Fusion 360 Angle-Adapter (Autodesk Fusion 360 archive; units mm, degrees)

design "Angle-Adapter" references "Base"
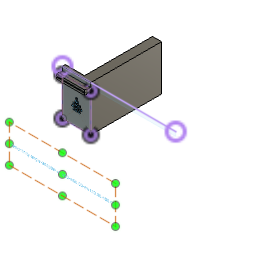
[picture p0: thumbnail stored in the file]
parameter "angle" = 90
parameter "width" = 50
parameter "extension_width" = 120
parameter "height" = 80
parameter "wall_thickness" = 5
component_insert "Component Insert"
sketch "Reference" plane through (0, 55.6118, 0) normal (0, 1, 0) x axis (-1, 0, 0)
  line L1 (0, 52.6059) -> (-200, 52.6059)
  line L2 (0, 60) -> (0, 52.6059)
  line L3 (-200, 60) -> (0, 60)
  line L4 (-200, 52.6059) -> (-200, 60)
  line L5 (-200, 60) -> (0, 60)
sketch "Base" plane through (0, 55.6118, 0) normal (0, 1, 0) x axis (-1, 0, 0)
  line L1 (-50, 60) -> (0, 60)
  line L2 (-50, -20) -> (-50, 60)
  line L3 (0, -20) -> (0, 60)
  line L4 (-50, -20) -> (0, -20)
  point P2 (0, 60)
  point P3 (-50, 60)
  point P4 (-50, -20)
  point P5 (0, -20)
  horizontal L1
  perpendicular L1 L2
  perpendicular L1 L3
  dimension "d5" distance P2 P3 = 50 (= "width")
  dimension "d7" distance P3 P4 = 80 (= "height")
  dimension "d8" distance P2 P5 = 80 (= "height")
extrude "Extrude1" new body sketch "Base" along normal blind 5 (= "wall_thickness")
extrude "Extrude2" new body of existing geometry blind 19
extrude "Extrude3" add of existing geometry to an object
extrude "Extrude4" cut of existing geometry to an object
work_plane "WorkPlane1" RotateAngle 90 (= "angle")
sketch "Sketch3" plane through (50, 0, 0) normal (1, 0, 0) x axis (0, 1, 0)
  line L1 (60.6118, -20) -> (60.6118, 60)
  line L2 (180.6118, 60) -> (60.6118, 60)
  line L3 (180.6118, -20) -> (180.6118, 60)
  line L4 (60.6118, -20) -> (180.6118, -20)
  line L5 (60.6118, 60) -> (60.6118, -20)
  point P2 (60.6118, 60)
  point P4 (60.6118, 60)
  point P3 (60.6118, -20)
  point P7 (60.6118, -20)
  point P5 (180.6118, 60)
  point P6 (180.6118, -20)
  coincident P2 P4
  perpendicular L1 L2
  perpendicular L2 L3
  coincident P3 P7
  dimension "d19" distance P4 P5 = 120 (= "extension_width")
  dimension "d20" distance P5 P6 = 80 (= "height")
extrude "Extrude5" add sketch "Sketch3" against normal blind 16 (magnitude of "( 11 mm + wall_thickness ) * -1")
extrude "Extrude6" add of existing geometry to an object
sketch "Sketch4" plane through (-0.5, 0, 0) normal (-1, 0, 0) x axis (0, -1, 0)
  line L1 (-28.6118, 45.5559) -> (-28.6118, 48.9559)
  line L2 (-33.1118, 45.5559) -> (-28.6118, 45.5559)
  line L3 (-33.1118, 47.0059) -> (-33.1118, 45.5559)
  line L4 (-39.6118, 47.0059) -> (-33.1118, 47.0059)
  line L5 (-39.6118, 39.6118) -> (-39.6118, 47.0059)
  line L6 (-22.1725, 22.1725) -> (-39.6118, 39.6118)
  line L7 (-19.6118, 60) -> (-19.6118, 23.2332)
  line L8 (-39.6118, 60) -> (-19.6118, 60)
  line L9 (-39.6118, 52.6059) -> (-39.6118, 60)
  line L10 (-33.1118, 52.6059) -> (-39.6118, 52.6059)
  line L11 (-33.1118, 54.0559) -> (-33.1118, 52.6059)
  line L12 (-28.6118, 54.0559) -> (-33.1118, 54.0559)
  line L13 (-28.6118, 50.6559) -> (-28.6118, 54.0559)
  line L14 (-33.1118, 52.6059) -> (-39.6118, 52.6059)
  line L15 (-33.1118, 52.6059) -> (-33.1118, 54.0559)
  line L16 (-33.1118, 54.0559) -> (-28.6118, 54.0559)
  line L17 (-33.1118, 45.5559) -> (-28.6118, 45.5559)
  line L18 (-33.1118, 47.0059) -> (-33.1118, 45.5559)
  line L19 (-33.1118, 47.0059) -> (-39.6118, 47.0059)
  line L20 (-28.6118, 45.5559) -> (-28.6118, 49.8059)
  line L21 (-28.6118, 54.0559) -> (-28.6118, 49.8059)
  line L22 (-39.6118, 47.0059) -> (-39.6118, 52.6059)
  arc A1 centre (-28.6118, 49.8059) radius 0.85 clockwise from (-28.6118, 50.6559) to (-28.6118, 48.9559)
  arc A2 centre (-21.1118, 23.2332) radius 1.5 clockwise from (-19.6118, 23.2332) to (-22.1725, 22.1725)
  point P15 (-39.6118, 52.6059)
  point P29 (-39.6118, 52.6059)
  point P8 (-39.6118, 47.0059)
  point P30 (-39.6118, 47.0059)
  coincident P15 P29
  coincident P8 P30
sketch "Sketch5" plane through (0, 180.6118, 0) normal (0, 1, 0) x axis (-1, 0, 0)
  line L1 (-50, -20) -> (-50, 60)
  line L2 (-34, -20) -> (-50, -20)
  line L3 (-34, 60) -> (-34, -20)
  line L4 (-50, 60) -> (-34, 60)
  line L5 (0, 52.6059) -> (-200, 52.6059)
  line L6 (-34, -20) -> (-34, 60)
  line L7 (-34, 44) -> (-34, 52.6059)
  line L8 (-40.5, 52.6059) -> (-34, 52.6059)
  line L9 (-40.5, 54.0559) -> (-40.5, 52.6059)
  line L10 (-45, 54.0559) -> (-40.5, 54.0559)
  line L11 (-45, 45.5559) -> (-45, 54.0559)
  line L12 (-40.5, 45.5559) -> (-45, 45.5559)
  line L13 (-40.5, 47.0059) -> (-40.5, 45.5559)
  line L14 (-34, 46.9975) -> (-40.5, 47.0059)
  line L15 (-34, 46.9975) -> (-34, 52.6059)
  point P10 (-34, 52.6059)
  point P11 (-34, 44)
  point P18 (-34, 46.9975)
  point P12 (-40.5, 52.6059)
  point P13 (-40.5, 54.0559)
  point P14 (-45, 54.0559)
  point P15 (-45, 45.5559)
  coincident L5 P10
  coincident L3 P10
  coincident L6 P11
  perpendicular L5 L7
  perpendicular L7 L8
  perpendicular L8 L9
  perpendicular L9 L10
  perpendicular L5 L11
  perpendicular L11 L12
  equal L10 L12
  perpendicular L12 L13
  equal L9 L13
  coincident L7 P18
  dimension "d29" distance P10 P12 = 6.5
  dimension "d30" distance P12 P13 = 1.45
  dimension "d31" distance P13 P14 = 4.5
  dimension "d32" distance P14 P15 = 8.5
extrude "Extrude9" cut sketch "Sketch5" profile of L3 L5 L6 L8 L9 L10 L11 L12 L13 L14 L15 along a picked direction to an object
sketch "Text" plane through (0, 55.6118, 0) normal (0, -1, 0) x axis (1, 0, 0)
  dimension "d35" = 3
extrude "Extrude10" cut sketch "Text" against normal blind 2
sketch "Filename" plane through (0, 0, 0) normal (0, 1, 0) x axis (1, 0, 0)
  dimension "d38" = 5

design "Base"
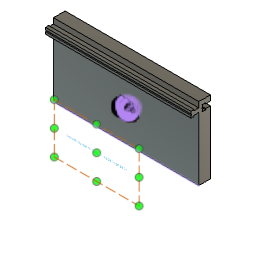
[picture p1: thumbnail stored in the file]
parameter "wall_anchor_height" = 60
parameter "wall_anchor_width" = 20
parameter "wall_anchor_angle" = 45
parameter "width_per_slot" = 40
parameter "slot_inner_width" = 8.5
parameter "slot_inner_height" = 4.5
parameter "slot_outer_width" = 5.6
parameter "slot_outer_height" = 6.5
parameter "slot_dept" = 15
parameter "print_tolerance" = 0.12
parameter "base_plate_thickness" = 16
parameter "base_plate_slot_height" = 50
parameter "wall_anchor_angle_rounded_border" = 1.5
parameter "base_plate_screw_hole_diameter" = 4
parameter "base_plate_screw_head_diameter" = 8
parameter "base_plate_screw_head_height" = 4
parameter "base_plate_screw_hole_side_distance" = 7
parameter "slot_screw_head_width" = 4.42 (= "4.3 mm + print_tolerance")
parameter "slot_screw_thread_width" = 2.12 (= "2 mm + print_tolerance")
parameter "slot_screw_head_height" = 2.12 (= "2 mm + print_tolerance")
parameter "width" = 200
parameter "filament_hole_width" = 1.7
parameter "plate_height" = 80
sketch "Side" plane through (0, 0, 0) normal (1, 0, 0) x axis (0, 1, 0)
  line L1 (39.6118, 0) -> (19.6118, 0)
  line L2 (39.6118, 60) -> (39.6118, 0)
  line L3 (19.6118, 60) -> (39.6118, 60)
  line L4 (19.6118, 0) -> (19.6118, 60)
  line L5 (39.6118, 39.6118) -> (0, 0)
  line L6 (56.0196, 0) -> (0, 0)
  point P1 (0, 0)
  point P6 (0, 0)
  point P7 (39.6118, 39.6118)
  point P2 (19.6118, 0)
  point P3 (39.6118, 0)
  point P5 (19.6118, 60)
  horizontal L1
  vertical L2
  horizontal L3
  vertical L4
  horizontal L6
  coincident P1 P6
  coincident L2 P7
  dimension "d4" distance P2 P3 = 20 (= "wall_anchor_width")
  dimension "d5" distance P2 P5 = 60 (= "wall_anchor_height")
  dimension "d6" angle L5 L6 = 45 (= "wall_anchor_angle")
extrude "Extrude1" new body sketch "Side" profile of L1 L2 L3 L4 L5 along normal blind 40 (= "width_per_slot")
sketch "Slot LeftToRight" plane through (0, 0, 0) normal (-1, 0, 0) x axis (0, -1, 0)
  line L1 (-19.6118, 60) -> (-19.6118, 19.6118)
  line L2 (-39.6118, 60) -> (-19.6118, 60)
  line L3 (-39.6118, 39.6118) -> (-39.6118, 60)
  line L4 (-19.6118, 19.6118) -> (-39.6118, 39.6118)
  line L5 (-39.6118, 52.6059) -> (-39.6118, 49.8059)
  line L6 (-39.6118, 47.0059) -> (-39.6118, 49.8059)
  line L7 (-33.1118, 52.6059) -> (-39.6118, 52.6059)
  line L8 (-28.6118, 49.8059) -> (-39.6118, 49.8059)
  line L9 (-28.6118, 54.0559) -> (-28.6118, 49.8059)
  line L10 (-33.1118, 54.0559) -> (-28.6118, 54.0559)
  line L11 (-33.1118, 52.6059) -> (-33.1118, 54.0559)
  line L12 (-28.6118, 45.5559) -> (-28.6118, 49.8059)
  line L13 (-33.1118, 45.5559) -> (-28.6118, 45.5559)
  line L14 (-33.1118, 47.0059) -> (-33.1118, 45.5559)
  line L15 (-33.1118, 47.0059) -> (-39.6118, 47.0059)
  point P6 (-39.6118, 49.8059)
  point P7 (-39.6118, 52.6059)
  point P17 (-39.6118, 47.0059)
  point P9 (-33.1118, 52.6059)
  point P16 (-33.1118, 47.0059)
  point P10 (-28.6118, 49.8059)
  point P13 (-28.6118, 49.8059)
  point P11 (-28.6118, 54.0559)
  point P14 (-28.6118, 45.5559)
  point P12 (-33.1118, 54.0559)
  point P15 (-33.1118, 45.5559)
  midpoint L3 P6
  parallel L3 L5
  parallel L3 L6
  perpendicular L3 L7
  perpendicular L6 L8
  perpendicular L8 L9
  perpendicular L9 L10
  symmetric P7 L8 P17
  symmetric P9 L8 P16
  symmetric P10 L8 P13
  symmetric L8 P11 P14
  symmetric L8 P12 P15
  dimension "d80" distance P6 P7 = 2.8 (= "slot_outer_width / 2")
  dimension "d82" distance P7 P9 = 6.5 (= "slot_outer_height")
  dimension "d84" distance P6 P10 = 11 (= "slot_outer_height + slot_inner_height")
  dimension "d85" distance P10 P11 = 4.25 (= "slot_inner_width / 2")
  dimension "d86" distance P11 P12 = 4.5 (= "slot_inner_height")
extrude "Extrude3" cut sketch "Slot LeftToRight" profile of L3 L5 L6 L7 L9 L10 L11 L12 L13 L14 L15 against normal blind 40 (magnitude of "width_per_slot * -1")
sketch "Plate" plane through (0, 39.6118, 0) normal (0, 1, 0) x axis (-1, 0, 0)
  line L1 (0, 39.6118) -> (-40, 39.6118)
  line L2 (-40, 60) -> (0, 60)
  line L3 (0, 10) -> (0, 60)
  line L4 (-40, 10) -> (-40, 60)
  line L5 (-40, 10) -> (0, 10)
  line L6 (-40, 47.0059) -> (0, 47.0059)
  line L7 (-40, 52.6059) -> (-40, 60)
  line L8 (0, 60) -> (0, 52.6059)
  line L9 (0, 52.6059) -> (-40, 52.6059)
  line L10 (-40, 60) -> (0, 60)
  line L11 (-40, 39.6118) -> (-40, 47.0059)
  line L12 (0, 47.0059) -> (0, 39.6118)
  point P2 (0, 60)
  point P3 (-40, 60)
  point P4 (0, 10)
  point P5 (-40, 10)
  perpendicular L1 L3
  perpendicular L1 L4
  dimension "d36" distance P2 P3 = 40 (= "width_per_slot")
  dimension "d37" distance P2 P4 = 50 (= "base_plate_slot_height")
  dimension "d39" distance P3 P5 = 50 (= "base_plate_slot_height")
extrude "Extrude6" new body sketch "Plate" profile of L1 L2 L3 L4 L5 L6 L7 L8 L9 L10 along normal blind 16 (= "base_plate_thickness") bodies "Base plate with slot"
sketch "Slot" plane through (0, 0, 0) normal (-1, 0, 0) x axis (0, -1, 0)
  line L1 (-19.6118, 60) -> (-19.6118, 19.6118)
  line L2 (-39.6118, 60) -> (-19.6118, 60)
  line L3 (-39.6118, 52.6059) -> (-39.6118, 60)
  line L4 (-33.1118, 52.6059) -> (-39.6118, 52.6059)
  line L5 (-33.1118, 54.0559) -> (-33.1118, 52.6059)
  line L6 (-28.6118, 54.0559) -> (-33.1118, 54.0559)
  line L7 (-28.6118, 45.5559) -> (-28.6118, 54.0559)
  line L8 (-33.1118, 45.5559) -> (-28.6118, 45.5559)
  line L9 (-33.1118, 47.0059) -> (-33.1118, 45.5559)
  line L10 (-39.6118, 47.0059) -> (-33.1118, 47.0059)
  line L11 (-39.6118, 39.6118) -> (-39.6118, 47.0059)
  line L12 (-19.6118, 19.6118) -> (-39.6118, 39.6118)
  line L13 (-33.1118, 52.6059) -> (-39.6118, 52.6059)
  line L14 (-33.1118, 54.0559) -> (-33.1118, 52.6059)
  line L15 (-28.6118, 54.0559) -> (-33.1118, 54.0559)
  line L16 (-28.6118, 45.5559) -> (-28.6118, 54.0559)
  line L17 (-33.1118, 45.5559) -> (-28.6118, 45.5559)
  line L18 (-33.1118, 47.0059) -> (-33.1118, 45.5559)
  line L19 (-39.6118, 47.0059) -> (-33.1118, 47.0059)
  line L20 (-39.6118, 10) -> (-39.6118, 60)
  line L21 (-32.9918, 52.4859) -> (-39.6118, 52.4859)
  line L22 (-32.9918, 53.9359) -> (-32.9918, 52.4859)
  line L23 (-28.7318, 53.9359) -> (-32.9918, 53.9359)
  line L24 (-28.7318, 45.6759) -> (-28.7318, 53.9359)
  line L25 (-32.9918, 45.6759) -> (-28.7318, 45.6759)
  line L26 (-32.9918, 47.1259) -> (-32.9918, 45.6759)
  line L27 (-39.6118, 47.1259) -> (-32.9918, 47.1259)
  line L28 (-33.1118, 52.6059) -> (-39.6118, 52.6059)
  line L29 (-33.1118, 52.6059) -> (-33.1118, 54.0559)
  line L30 (-28.6118, 54.0559) -> (-33.1118, 54.0559)
  line L31 (-28.6118, 45.5559) -> (-28.6118, 54.0559)
  line L32 (-33.1118, 45.5559) -> (-28.6118, 45.5559)
  line L33 (-33.1118, 47.0059) -> (-33.1118, 45.5559)
  line L34 (-39.6118, 47.0059) -> (-33.1118, 47.0059)
  line L35 (-39.6118, 47.0059) -> (-39.6118, 52.6059)
  line L36 (-49.1118, 52.6059) -> (-55.6118, 52.6059)
  line L37 (-49.1118, 52.6059) -> (-49.1118, 54.0559)
  line L38 (-44.6118, 54.0559) -> (-49.1118, 54.0559)
  line L39 (-44.6118, 45.5559) -> (-44.6118, 54.0559)
  line L40 (-49.1118, 45.5559) -> (-44.6118, 45.5559)
  line L41 (-49.1118, 47.0059) -> (-49.1118, 45.5559)
  line L42 (-55.6118, 47.0059) -> (-49.1118, 47.0059)
  line L43 (-55.6118, 47.0059) -> (-55.6118, 52.6059)
  point P15 (-39.6118, 52.6059)
  point P33 (-39.6118, 52.6059)
  point P16 (-33.1118, 52.6059)
  point P34 (-33.1118, 52.6059)
  point P17 (-33.1118, 54.0559)
  point P35 (-33.1118, 54.0559)
  point P36 (-33.1118, 52.6059)
  point P18 (-28.6118, 54.0559)
  point P37 (-28.6118, 54.0559)
  point P19 (-28.6118, 45.5559)
  point P38 (-28.6118, 45.5559)
  point P10 (-28.6118, 45.5559)
  point P39 (-28.6118, 45.5559)
  point P11 (-33.1118, 45.5559)
  point P40 (-33.1118, 45.5559)
  point P41 (-33.1118, 45.5559)
  point P12 (-33.1118, 47.0059)
  point P42 (-33.1118, 47.0059)
  point P21 (-33.1118, 47.0059)
  point P43 (-33.1118, 47.0059)
  point P22 (-39.6118, 47.0059)
  point P44 (-39.6118, 47.0059)
  point P45 (-39.6118, 52.6059)
  point P46 (-39.6118, 47.0059)
  coincident P15 P33
  coincident P16 P34
  coincident P17 P35
  coincident P16 P36
  coincident P18 P37
  coincident P19 P38
  coincident P10 P39
  coincident P11 P40
  coincident P11 P41
  coincident P12 P42
  coincident P21 P43
  coincident P22 P44
  coincident P15 P45
  coincident P22 P46
  dimension "d91" = 0.12 (= "print_tolerance")
  dimension "d96" R-Pattern1-uDistance = -16 (= "base_plate_thickness * -1")
  dimension "d97" R-Pattern1-vDistance = 0
extrude "Extrude7" add sketch "Slot" profile of L20 L24 L23 L27 L22 L25 L26 L21 against normal blind 40 (magnitude of "width_per_slot * -1")
extrude "Extrude8" cut sketch "Slot" profile of L36 L37 L38 L39 L40 L41 L42 L43 no distance stored
sketch "Sketch3" plane through (0, 0, 0) normal (-1, 0, 0) x axis (0, -1, 0)
  line L1 (-32.9918, 47.1259) -> (-39.6118, 47.1259)
  line L2 (-32.9918, 45.6759) -> (-32.9918, 47.1259)
  line L3 (-28.7318, 45.6759) -> (-32.9918, 45.6759)
  line L4 (-28.7318, 53.9359) -> (-28.7318, 45.6759)
  line L5 (-32.9918, 53.9359) -> (-28.7318, 53.9359)
  line L6 (-32.9918, 52.4859) -> (-32.9918, 53.9359)
  line L7 (-39.6118, 52.4859) -> (-32.9918, 52.4859)
  line L8 (-44.6118, 45.5559) -> (-44.6118, 54.0559)
  line L9 (-32.9918, 52.4859) -> (-39.6118, 52.4859)
  line L10 (-32.9918, 53.9359) -> (-32.9918, 52.4859)
  line L11 (-28.7318, 53.9359) -> (-32.9918, 53.9359)
  line L12 (-28.7318, 45.6759) -> (-28.7318, 53.9359)
  line L13 (-32.9918, 45.6759) -> (-28.7318, 45.6759)
  line L14 (-32.9918, 47.1259) -> (-32.9918, 45.6759)
  line L15 (-39.6118, 47.1259) -> (-32.9918, 47.1259)
  line L16 (-39.6118, 47.1259) -> (-39.6118, 52.4859)
  line L17 (-55.6118, 52.4859) -> (-48.9918, 52.4859)
  line L18 (-48.9918, 52.4859) -> (-48.9918, 53.9359)
  line L19 (-48.9918, 53.9359) -> (-44.7318, 53.9359)
  line L20 (-44.7318, 45.6759) -> (-44.7318, 53.9359)
  line L21 (-48.9918, 45.6759) -> (-44.7318, 45.6759)
  line L22 (-48.9918, 47.1259) -> (-48.9918, 45.6759)
  line L23 (-55.6118, 47.1259) -> (-48.9918, 47.1259)
  line L24 (-55.6118, 47.1259) -> (-55.6118, 52.4859)
  line L25 (-55.6118, 47.0059) -> (-49.1118, 47.0059)
  line L26 (-55.6118, 10) -> (-55.6118, 47.0059)
  line L27 (-39.6118, 10) -> (-55.6118, 10)
  line L28 (-39.6118, 47.1259) -> (-39.6118, 10)
  line L29 (-39.6118, 60) -> (-39.6118, 52.4859)
  line L30 (-55.6118, 60) -> (-39.6118, 60)
  line L31 (-55.6118, 52.6059) -> (-55.6118, 60)
  line L32 (-49.1118, 52.6059) -> (-55.6118, 52.6059)
  line L33 (-49.1118, 54.0559) -> (-49.1118, 52.6059)
  line L34 (-44.6118, 54.0559) -> (-49.1118, 54.0559)
  line L35 (-49.1118, 45.5559) -> (-44.6118, 45.5559)
  line L36 (-49.1118, 47.0059) -> (-49.1118, 45.5559)
  point P9 (-39.6118, 52.4859)
  point P20 (-39.6118, 52.4859)
  point P19 (-39.6118, 47.1259)
  point P21 (-39.6118, 47.1259)
  coincident P9 P20
  coincident P19 P21
  dimension "d105" R-Pattern1-vDistance = 0
extrude "Extrude3" new body sketch "Sketch3" profile of L17 L18 L19 L20 L21 L22 L23 L24 against normal blind 40 (magnitude of "width_per_slot * -1")
sketch "Screw hole" plane through (0, 28.6118, 0) normal (0, 1, 0) x axis (-1, 0, 0)
  line L1 (0, 54.0559) -> (0, 45.5559)
  line L2 (-40, 54.0559) -> (0, 54.0559)
  line L3 (-40, 45.5559) -> (-40, 54.0559)
  line L4 (0, 45.5559) -> (-40, 45.5559)
  line L5 (0, 45.5559) -> (-40, 54.0559)
  line L6 (-40, 45.5559) -> (0, 54.0559)
  circle C1 centre (-20, 49.8059) radius 2.21
  circle C2 centre (-20, 49.8059) radius 1.06
  point P4 (-40, 54.0559)
  point P6 (-40, 54.0559)
  point P2 (0, 45.5559)
  point P7 (0, 45.5559)
  point P3 (0, 54.0559)
  point P8 (0, 54.0559)
  point P5 (-40, 45.5559)
  point P9 (-40, 45.5559)
  point P10 (-20, 49.8059)
  coincident P4 P6
  coincident P2 P7
  coincident P3 P8
  coincident P5 P9
  midpoint L5 P10
  concentric C1 C2
  dimension "d119" diameter C1 = 4.42 (= "slot_screw_head_width")
  dimension "d120" diameter C2 = 2.12 (= "slot_screw_thread_width")
extrude "Extrude4" cut sketch "Screw hole" profile of C2 against normal blind 2000
extrude "Extrude5" cut sketch "Screw hole" profile of C1 C2 no distance stored
fillet "Fillet1" radius 1.5 (= "wall_anchor_angle_rounded_border")
work_plane "WorkPlane1" sketch "Slot LeftToRight" AlongDistance -20 (= "-width_per_slot / 2")
sketch "Screw head" plane through (20, 0, 0) normal (-1, 0, 0) x axis (0, -1, 0)
  line L1 (-28.6118, 52.0159) -> (-28.6118, 47.5959)
  line L2 (-26.4918, 52.0159) -> (-26.4918, 47.5959)
  line L3 (-26.4918, 48.7459) -> (-26.4918, 50.8659)
  line L4 (-26.4918, 50.8659) -> (-28.6118, 52.0159)
  line L5 (-26.4918, 52.0159) -> (-28.6118, 52.0159)
  point P3 (-28.6118, 52.0159)
  point P8 (-28.6118, 52.0159)
  point P6 (-26.4918, 50.8659)
  point P9 (-26.4918, 50.8659)
  point P10 (-28.6118, 52.0159)
  point P5 (-26.4918, 52.0159)
  point P11 (-26.4918, 52.0159)
  coincident P3 P8
  coincident P6 P9
  coincident P3 P10
  coincident P5 P11
revolve "Revolve1" sketch "Screw head" AlongAngle 360
sketch "Plate" plane through (0, 39.6118, 0) normal (0, 1, 0) x axis (-1, 0, 0)
  line L1 (0, 39.6118) -> (-40, 39.6118)
  line L2 (-40, 60) -> (0, 60)
  line L3 (0, 10) -> (0, 60)
  line L4 (-40, 10) -> (-40, 60)
  line L5 (-40, 10) -> (0, 10)
  line L6 (-40, 47.0059) -> (0, 47.0059)
  line L7 (-40, 39.6118) -> (-40, 47.0059)
  line L8 (0, 47.0059) -> (0, 39.6118)
  line L9 (0, 52.6059) -> (-40, 52.6059)
  line L10 (-40, 60) -> (0, 60)
  line L11 (0, 60) -> (0, 52.6059)
  line L12 (-40, 52.6059) -> (-40, 60)
  point P2 (0, 60)
  point P3 (-40, 60)
  point P4 (0, 10)
  point P5 (-40, 10)
  perpendicular L1 L3
  perpendicular L1 L4
  dimension "d36_1" distance P2 P3 = 40 (= "width_per_slot")
  dimension "d37_1" distance P2 P4 = 50 (= "base_plate_slot_height")
  dimension "d39_1" distance P3 P5 = 50 (= "base_plate_slot_height")
extrude "Extrude6" new body sketch "Plate" profile of L1 L2 L3 L4 L5 L6 L7 L8 L9 L10 along normal blind 16 (= "base_plate_thickness") named "d89_1" bodies "Base plate with slot"
sketch "Slot" plane through (0, 0, 0) normal (-1, 0, 0) x axis (0, -1, 0)
  line L1 (-19.6118, 60) -> (-19.6118, 23.2332)
  line L2 (-39.6118, 60) -> (-19.6118, 60)
  line L3 (-39.6118, 52.6059) -> (-39.6118, 60)
  line L4 (-33.1118, 52.6059) -> (-39.6118, 52.6059)
  line L5 (-33.1118, 54.0559) -> (-33.1118, 52.6059)
  line L6 (-28.6118, 54.0559) -> (-33.1118, 54.0559)
  line L7 (-28.6118, 45.5559) -> (-28.6118, 54.0559)
  line L8 (-33.1118, 45.5559) -> (-28.6118, 45.5559)
  line L9 (-33.1118, 47.0059) -> (-33.1118, 45.5559)
  line L10 (-39.6118, 47.0059) -> (-33.1118, 47.0059)
  line L11 (-39.6118, 39.6118) -> (-39.6118, 47.0059)
  line L12 (-22.1725, 22.1725) -> (-39.6118, 39.6118)
  line L13 (-33.1118, 52.6059) -> (-39.6118, 52.6059)
  line L14 (-33.1118, 54.0559) -> (-33.1118, 52.6059)
  line L15 (-28.6118, 54.0559) -> (-33.1118, 54.0559)
  line L16 (-28.6118, 45.5559) -> (-28.6118, 54.0559)
  line L17 (-33.1118, 45.5559) -> (-28.6118, 45.5559)
  line L18 (-33.1118, 47.0059) -> (-33.1118, 45.5559)
  line L19 (-39.6118, 47.0059) -> (-33.1118, 47.0059)
  line L20 (-39.6118, 10) -> (-39.6118, 60)
  line L21 (-32.9918, 52.4859) -> (-39.6118, 52.4859)
  line L22 (-32.9918, 53.9359) -> (-32.9918, 52.4859)
  line L23 (-28.7318, 53.9359) -> (-32.9918, 53.9359)
  line L24 (-28.7318, 45.6759) -> (-28.7318, 53.9359)
  line L25 (-32.9918, 45.6759) -> (-28.7318, 45.6759)
  line L26 (-32.9918, 47.1259) -> (-32.9918, 45.6759)
  line L27 (-39.6118, 47.1259) -> (-32.9918, 47.1259)
  line L28 (-33.1118, 52.6059) -> (-39.6118, 52.6059)
  line L29 (-33.1118, 52.6059) -> (-33.1118, 54.0559)
  line L30 (-28.6118, 54.0559) -> (-33.1118, 54.0559)
  line L31 (-28.6118, 45.5559) -> (-28.6118, 54.0559)
  line L32 (-33.1118, 45.5559) -> (-28.6118, 45.5559)
  line L33 (-33.1118, 47.0059) -> (-33.1118, 45.5559)
  line L34 (-39.6118, 47.0059) -> (-33.1118, 47.0059)
  line L35 (-39.6118, 47.0059) -> (-39.6118, 52.6059)
  line L36 (-49.1118, 52.6059) -> (-55.6118, 52.6059)
  line L37 (-49.1118, 52.6059) -> (-49.1118, 54.0559)
  line L38 (-44.6118, 54.0559) -> (-49.1118, 54.0559)
  line L39 (-44.6118, 45.5559) -> (-44.6118, 54.0559)
  line L40 (-49.1118, 45.5559) -> (-44.6118, 45.5559)
  line L41 (-49.1118, 47.0059) -> (-49.1118, 45.5559)
  line L42 (-55.6118, 47.0059) -> (-49.1118, 47.0059)
  line L43 (-55.6118, 47.0059) -> (-55.6118, 52.6059)
  arc A1 centre (-21.1118, 23.2332) radius 1.5 clockwise from (-19.6118, 23.2332) to (-22.1725, 22.1725)
  point P15 (-39.6118, 52.6059)
  point P33 (-39.6118, 52.6059)
  point P16 (-33.1118, 52.6059)
  point P34 (-33.1118, 52.6059)
  point P17 (-33.1118, 54.0559)
  point P35 (-33.1118, 54.0559)
  point P36 (-33.1118, 52.6059)
  point P18 (-28.6118, 54.0559)
  point P37 (-28.6118, 54.0559)
  point P19 (-28.6118, 45.5559)
  point P38 (-28.6118, 45.5559)
  point P10 (-28.6118, 45.5559)
  point P39 (-28.6118, 45.5559)
  point P11 (-33.1118, 45.5559)
  point P40 (-33.1118, 45.5559)
  point P41 (-33.1118, 45.5559)
  point P12 (-33.1118, 47.0059)
  point P42 (-33.1118, 47.0059)
  point P21 (-33.1118, 47.0059)
  point P43 (-33.1118, 47.0059)
  point P22 (-39.6118, 47.0059)
  point P44 (-39.6118, 47.0059)
  point P45 (-39.6118, 52.6059)
  point P46 (-39.6118, 47.0059)
  coincident P15 P33
  coincident P16 P34
  coincident P17 P35
  coincident P16 P36
  coincident P18 P37
  coincident P19 P38
  coincident P10 P39
  coincident P11 P40
  coincident P11 P41
  coincident P12 P42
  coincident P21 P43
  coincident P22 P44
  coincident P15 P45
  coincident P22 P46
  dimension "d91_1" = 0.12 (= "print_tolerance")
  dimension "d96_1" R-Pattern1-uDistance = -16 (= "base_plate_thickness * -1")
  dimension "d97_1" R-Pattern1-vDistance = 0
extrude "Extrude8" cut sketch "Slot" profile of L36 L37 L38 L39 L40 L41 L42 L43 no distance stored
sketch "Screw" plane through (0, 55.6118, 0) normal (0, 1, 0) x axis (-1, 0, 0)
  line L1 (-40, 47.0059) -> (0, 47.0059)
  line L2 (-40, 10) -> (-40, 47.0059)
  line L3 (0, 10) -> (-40, 10)
  line L4 (0, 47.0059) -> (0, 10)
  line L5 (-33, 17) -> (-33, 40.0059)
  line L6 (-7, 17) -> (-33, 17)
  line L7 (-7, 40.0059) -> (-7, 17)
  line L8 (-33, 40.0059) -> (-7, 40.0059)
  circle C1 centre (-33, 17) radius 4
  circle C2 centre (-33, 17) radius 2
  point P7 (-33, 17)
  point P10 (-33, 17)
  coincident P7 P10
  concentric C1 C2
  dimension "d127" = -7 (= "base_plate_screw_hole_side_distance * -1")
  dimension "d128" diameter C1 = 8
  dimension "d129" diameter C2 = 4
rectangular_pattern "R-Pattern2" countU 5 (= "floor(( width / mm ) / ( width_per_slot / cm * 10 ))") uSpaceDistance 40 (= "width_per_slot") vSpaceDistance 0 bodies "Wall anchor part (1)", "Wall anchor part (2)", "Wall anchor part (3)", "Wall anchor part (4)"
work_plane "WorkPlane2"
extrude "Extrude12" new body of existing geometry no distance stored
mirror "Mirror3" mirrorStitchTolerance 0.1
sketch "filename" plane through (0, 19.6118, 0) normal (0, -1, 0) x axis (1, 0, 0)
  dimension "d216" = 3
sketch "Text" plane through (0, 19.6118, 0) normal (0, -1, 0) x axis (1, 0, 0)
  line L1 (200.5, 60) -> (200.5, 23.2332)
  line L2 (200, 23.2332) -> (200, 60)
  line L3 (200.5, 23.2332) -> (200, 23.2332)
  line L4 (200.5, 60) -> (200.5, 23.2332)
  line L5 (200, 60) -> (200.5, 60)
  line L6 (0, 60) -> (0, 23.2332)
  line L7 (-0.5, 60) -> (0, 60)
  line L8 (-0.5, 23.2332) -> (-0.5, 60)
  line L9 (0, 23.2332) -> (-0.5, 23.2332)
  curve K1
  curve K2
  curve K3
  curve K4
  line L10 (80, 60) -> (40, 60)
  point P4 (200.5, 23.2332)
  point P2 (-0.5, 60)
  coincident P4
  coincident P2
  parallel K3 L10
  dimension "d229" Text1-Height = 3
extrude "Extrude19" cut sketch "Text" against normal blind 2
extrude "Extrude14" cut of existing geometry blind 80 (= "( width_per_slot - width ) / -2")
extrude "Extrude15" cut of existing geometry blind 80 (= "( width_per_slot - width ) / -2")
extrude "Extrude9" cut of existing geometry blind -39 (= "-width_per_slot + 1 mm")
extrude "Extrude10" add of existing geometry blind 199 (= "width - 1 mm")
extrude "Extrude13" cut of existing geometry blind -30
extrude "Extrude14" add of existing geometry blind 80 (= "plate_height")
sketch "Sketch7" plane through (0, 39.6118, 0) normal (0, -1, 0) x axis (1, 0, 0)
  dimension "d236" = 3
extrude "Extrude11" cut sketch "Sketch7" against normal blind 2
sketch "File name" plane through (0, 39.6118, 0) normal (0, -1, 0) x axis (1, 0, 0)
  line L1 (92.897, 7.4163) -> (92.6596, 7.4163)
  line L2 (92.897, 4.404) -> (92.897, 7.4163)
  line L3 (92.5286, 4.404) -> (92.897, 4.404)
  line L4 (92.5286, 6.7512) -> (92.5286, 4.404)
  curve K1 (92.1787, 6.4975) -> (92.5286, 6.7512)
  curve K2 (91.792, 6.3072) -> (92.1787, 6.4975)
  line L5 (91.792, 6.6632) -> (91.792, 6.3072)
  curve K3 (92.3322, 7.0152) -> (91.792, 6.6632)
  curve K4 (92.6596, 7.4163) -> (92.3322, 7.0152)
  line L6 (96.1242, 4.404) -> (96.5641, 6.0759)
  line L7 (95.7394, 4.404) -> (96.1242, 4.404)
  line L8 (95.0744, 6.5773) -> (95.7394, 4.404)
  line L9 (95.455, 6.5773) -> (95.0744, 6.5773)
  line L10 (95.8008, 5.3229) -> (95.455, 6.5773)
  line L11 (95.9297, 4.8563) -> (95.8008, 5.3229)
  curve K5 (96.0423, 5.3044) -> (95.9297, 4.8563)
  line L12 (96.3881, 6.5773) -> (96.0423, 5.3044)
  line L13 (96.7667, 6.5773) -> (96.3881, 6.5773)
  line L14 (97.0921, 5.3167) -> (96.7667, 6.5773)
  line L15 (97.2005, 4.9013) -> (97.0921, 5.3167)
  line L16 (97.3254, 5.3208) -> (97.2005, 4.9013)
  line L17 (97.6978, 6.5773) -> (97.3254, 5.3208)
  line L18 (98.0559, 6.5773) -> (97.6978, 6.5773)
  line L19 (97.3765, 4.404) -> (98.0559, 6.5773)
  line L20 (96.9939, 4.404) -> (97.3765, 4.404)
  line L21 (96.648, 5.7055) -> (96.9939, 4.404)
  line L22 (96.5641, 6.0759) -> (96.648, 5.7055)
  line L23 (94.9311, 5.3044) -> (94.9311, 5.6748)
  line L24 (93.7995, 5.3044) -> (94.9311, 5.3044)
  line L25 (93.7995, 5.6748) -> (93.7995, 5.3044)
  line L26 (94.9311, 5.6748) -> (93.7995, 5.6748)
  line L27 (90.4638, 4.404) -> (91.2865, 6.5773)
  line L28 (90.1201, 4.404) -> (90.4638, 4.404)
  line L29 (89.2933, 6.5773) -> (90.1201, 4.404)
  line L30 (89.6821, 6.5773) -> (89.2933, 6.5773)
  line L31 (90.1487, 5.2758) -> (89.6821, 6.5773)
  curve K6 (90.2879, 4.8379) -> (90.1487, 5.2758)
  curve K7 (90.425, 5.2512) -> (90.2879, 4.8379)
  line L32 (90.9079, 6.5773) -> (90.425, 5.2512)
  line L33 (91.2865, 6.5773) -> (90.9079, 6.5773)
  line L34 (0, 47.1259) -> (200, 47.1259)
  line L35 (0, -40) -> (0, 47.1259)
  line L36 (200, 47.1259) -> (200, -40)
  curve K8
  curve K9
  curve K10
  curve K11
  curve K12 (100.1944, 6.5834) -> (99.9427, 7.1769)
  line L37 (200, -40) -> (0, -40)
  line L38 (100.1985, 4.404) -> (100.1985, 4.758)
  curve K13 (99.9427, 7.1769) -> (99.2592, 7.4163)
  curve K14 (101.5716, 7.4163) -> (101.0273, 7.2403)
  line L39 (98.2156, 4.404) -> (100.1985, 4.404)
  curve K15 (96.1252, 1.9443) -> (95.4744, 1.6455)
  curve K16 (99.074, 1.5862) -> (99.1845, 1.9504)
  curve K17 (98.7425, 1.3488) -> (99.074, 1.5862)
  curve K18 (99.162, 1.0582) -> (98.7425, 1.3488)
  curve K19 (100.1207, 6.2294) -> (100.1944, 6.5834)
  curve K20 (102.296, 7.0377) -> (101.9952, 7.3181)
  curve K21 (102.4823, 6.5916) -> (102.296, 7.0377)
  curve K22 (102.5498, 5.8836) -> (102.4823, 6.5916)
  curve K23 (102.4413, 5.0302) -> (102.5498, 5.8836)
  curve K24 (103.2691, 2.0568) -> (103.1606, 1.2014)
  curve K25 (97.9014, 1.3488) -> (97.4778, 1.0786)
  curve K26 (106.4195, 5.8836) -> (106.7162, 4.6639)
  curve K27 (96.3871, 1.5002) -> (96.5078, 1.0991)
  curve K28 (99.3083, 5.3351) -> (99.8752, 5.8631)
  curve K29 (98.8827, 4.9566) -> (99.3083, 5.3351)
  curve K30 (98.7271, 4.758) -> (98.8827, 4.9566)
  curve K31 (100.7019, 6.7389) -> (100.5935, 5.8836)
  curve K32 (101.0273, 7.2403) -> (100.7019, 6.7389)
  curve K33 (98.2585, 4.6598) -> (98.2156, 4.404)
  curve K34 (98.5, 5.0589) -> (98.2585, 4.6598)
  curve K35 (99.6439, 6.1475) -> (98.983, 5.5132)
  curve K36 (99.8158, 6.5916) -> (99.6439, 6.1475)
  curve K37 (104.1388, -0.3293) -> (104.6832, -0.1533)
  curve K38 (108.8588, 6.7389) -> (108.7503, 5.8836)
  line L40 (92.7752, -1.111) -> (93.1436, -1.111)
  curve K39 (96.0495, 1.6271) -> (96.3871, 1.5002)
  curve K40 (95.7405, 1.5411) -> (96.0495, 1.6271)
  curve K41 (95.5358, 1.3119) -> (95.7405, 1.5411)
  curve K42 (95.4744, 0.9108) -> (95.5358, 1.3119)
  curve K43 (106.528, 6.7389) -> (106.4195, 5.8836)
  curve K44 (98.6637, 6.5098) -> (98.8254, 6.9518)
  curve K45 (98.5778, 7.1932) -> (98.2851, 6.5486)
  curve K46 (99.2592, 7.4163) -> (98.5778, 7.1932)
  curve K47 (102.116, 4.5289) -> (102.4413, 5.0302)
  curve K48 (101.5716, 4.3529) -> (102.116, 4.5289)
  curve K49 (100.8902, 4.6639) -> (101.5716, 4.3529)
  curve K50 (100.5935, 5.8836) -> (100.8902, 4.6639)
  line L41 (100.1985, 4.758) -> (98.7271, 4.758)
  curve K51 (98.983, 5.5132) -> (98.5, 5.0589)
  curve K52 (99.6583, 6.96) -> (99.8158, 6.5916)
  curve K53 (99.251, 7.1114) -> (99.6583, 6.96)
  curve K54 (98.8254, 6.9518) -> (99.251, 7.1114)
  line L42 (98.2851, 6.5486) -> (98.6637, 6.5098)
  curve K55 (99.8752, 5.8631) -> (100.1207, 6.2294)
  curve K56 (103.9025, 7.4163) -> (103.3581, 7.2403)
  curve K57 (104.3261, 7.3181) -> (103.9025, 7.4163)
  curve K58 (104.8131, 6.5916) -> (104.6269, 7.0377)
  curve K59 (104.8806, 5.8836) -> (104.8131, 6.5916)
  curve K60 (107.3977, 4.3529) -> (107.942, 4.5289)
  curve K61 (106.7162, 4.6639) -> (107.3977, 4.3529)
  line L43 (93.1436, -1.111) -> (93.1436, -0.053)
  line L44 (95.4744, -0.2781) -> (95.4744, 0.9108)
  line L45 (95.1061, -0.2781) -> (95.4744, -0.2781)
  curve K62 (98.9451, 2.505) -> (98.3128, 2.7342)
  curve K63 (99.1845, 1.9504) -> (98.9451, 2.505)
  line L46 (93.1108, 1.6128) -> (93.1108, 1.8952)
  curve K64 (101.9952, 7.3181) -> (101.5716, 7.4163)
  line L47 (105.8813, 4.404) -> (105.8813, 4.8235)
  line L48 (105.4618, 4.404) -> (105.8813, 4.404)
  line L49 (105.4618, 4.8235) -> (105.4618, 4.404)
  line L50 (105.8813, 4.8235) -> (105.4618, 4.8235)
  curve K65 (106.8533, 7.2403) -> (106.528, 6.7389)
  curve K66 (107.3977, 7.4163) -> (106.8533, 7.2403)
  curve K67 (107.8213, 7.3181) -> (107.3977, 7.4163)
  curve K68 (108.1221, 7.0377) -> (107.8213, 7.3181)
  curve K69 (108.3083, 6.5916) -> (108.1221, 7.0377)
  curve K70 (108.3759, 5.8836) -> (108.3083, 6.5916)
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  dimension "d239" Text1-Height = 3
sketch "Sketch4" plane through (40, 0, 0) normal (1, 0, 0) x axis (0, 1, 0)
  line L1 (44.7318, 53.9359) -> (48.9918, 53.9359)
  line L2 (44.7318, 45.6759) -> (44.7318, 53.9359)
  line L3 (48.9918, 45.6759) -> (44.7318, 45.6759)
  line L4 (48.9918, 47.1259) -> (48.9918, 45.6759)
  line L5 (55.6118, 47.1259) -> (48.9918, 47.1259)
  line L6 (55.6118, 52.4859) -> (55.6118, 47.1259)
  line L7 (48.9918, 52.4859) -> (55.6118, 52.4859)
  line L8 (48.9918, 53.9359) -> (48.9918, 52.4859)
  circle C1 centre (44.7318, 49.8059) radius 0.85
  point P10 (44.7318, 49.8059)
  midpoint L2 P10
  dimension "d241" diameter C1 = 1.7 (= "filament_hole_width")
extrude "Extrude4" cut sketch "Sketch4" profile of L2 C1 no distance stored
sketch "Sketch15" plane through (-0.5, 0, 0) normal (-1, 0, 0) x axis (0, -1, 0)
  line L1 (-19.6118, 60) -> (-19.6118, 23.2332)
  line L2 (-39.6118, 60) -> (-19.6118, 60)
  line L3 (-39.6118, 52.6059) -> (-39.6118, 60)
  line L4 (-33.1118, 52.6059) -> (-39.6118, 52.6059)
  line L5 (-33.1118, 54.0559) -> (-33.1118, 52.6059)
  line L6 (-28.6118, 54.0559) -> (-33.1118, 54.0559)
  line L7 (-28.6118, 45.5559) -> (-28.6118, 54.0559)
  line L8 (-33.1118, 45.5559) -> (-28.6118, 45.5559)
  line L9 (-33.1118, 47.0059) -> (-33.1118, 45.5559)
  line L10 (-39.6118, 47.0059) -> (-33.1118, 47.0059)
  line L11 (-39.6118, 39.6118) -> (-39.6118, 47.0059)
  line L12 (-22.1725, 22.1725) -> (-39.6118, 39.6118)
  arc A1 centre (-21.1118, 23.2332) radius 1.5 clockwise from (-19.6118, 23.2332) to (-22.1725, 22.1725)
  circle C1 centre (-28.6118, 49.8059) radius 0.85
  point P16 (-28.6118, 49.8059)
  midpoint L7 P16
  dimension "d244" diameter C1 = 1.7 (= "filament_hole_width")
sketch "Sketch9" plane through (200, 0, 0) normal (1, 0, 0) x axis (0, 1, 0)
  line L1 (49.1118, 47.0059) -> (55.6118, 47.0059)
  line L2 (49.1118, 45.5559) -> (49.1118, 47.0059)
  line L3 (44.6118, 45.5559) -> (49.1118, 45.5559)
  line L4 (44.6118, 54.0559) -> (44.6118, 45.5559)
  line L5 (49.1118, 54.0559) -> (44.6118, 54.0559)
  line L6 (49.1118, 52.6059) -> (49.1118, 54.0559)
  line L7 (55.6118, 52.6059) -> (49.1118, 52.6059)
  line L8 (55.6118, 47.0059) -> (55.6118, -40)
  line L9 (39.6118, 60) -> (55.6118, 60)
  line L10 (39.6118, 52.4859) -> (39.6118, 60)
  line L11 (32.9918, 52.4859) -> (39.6118, 52.4859)
  line L12 (32.9918, 53.9359) -> (32.9918, 52.4859)
  line L13 (28.7318, 53.9359) -> (32.9918, 53.9359)
  line L14 (28.7318, 45.6759) -> (28.7318, 53.9359)
  line L15 (32.9918, 45.6759) -> (28.7318, 45.6759)
  line L16 (32.9918, 47.1259) -> (32.9918, 45.6759)
  line L17 (39.6118, 47.1259) -> (32.9918, 47.1259)
  line L18 (55.6118, 60) -> (55.6118, 52.6059)
  line L19 (39.6118, -40) -> (39.6118, 47.1259)
  line L20 (55.6118, -40) -> (39.6118, -40)
  circle C1 centre (28.7318, 49.8059) radius 0.85
  circle C2 centre (44.6118, 49.8059) radius 0.85
  point P20 (28.7318, 49.8059)
  point P21 (44.6118, 49.8059)
  midpoint L14 P20
  midpoint L4 P21
  dimension "d247" diameter C1 = 1.7 (= "filament_hole_width")
  dimension "d250" diameter C2 = 1.7 (= "filament_hole_width")
extrude "Extrude12" cut sketch "Sketch9" profile of L4 L14 C1 C2 no distance stored
sketch "Sketch16" plane through (0, 19.6118, 0) normal (0, -1, 0) x axis (1, 0, 0)
  dimension "d253" = 3
extrude "Extrude22" cut sketch "Sketch16" against normal blind 2
extrude "Extrude23" cut sketch "Sketch15" profile of L7 C1 against normal blind 260 and along normal blind 80
sketch "Sketch17" plane through (0, 19.6118, 0) normal (0, -1, 0) x axis (1, 0, 0)
  dimension "d258" = 3
extrude "Extrude24" cut sketch "Sketch17" against normal blind 2
extrude "Extrude26" cut sketch "Text" against normal blind 2
extrude "Extrude27" cut sketch "Text" against normal blind 2
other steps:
create_component "CreateComponent1"
create_component "CreateComponent2"
create_component "CreateComponent3"
create_component "CreateComponent4"
named bodies: "Wall anchor part", "Base plate with slot", "Wall anchor part (1)", "Wall anchor part (2)", "Wall anchor part (3)", "Wall anchor part (4)"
